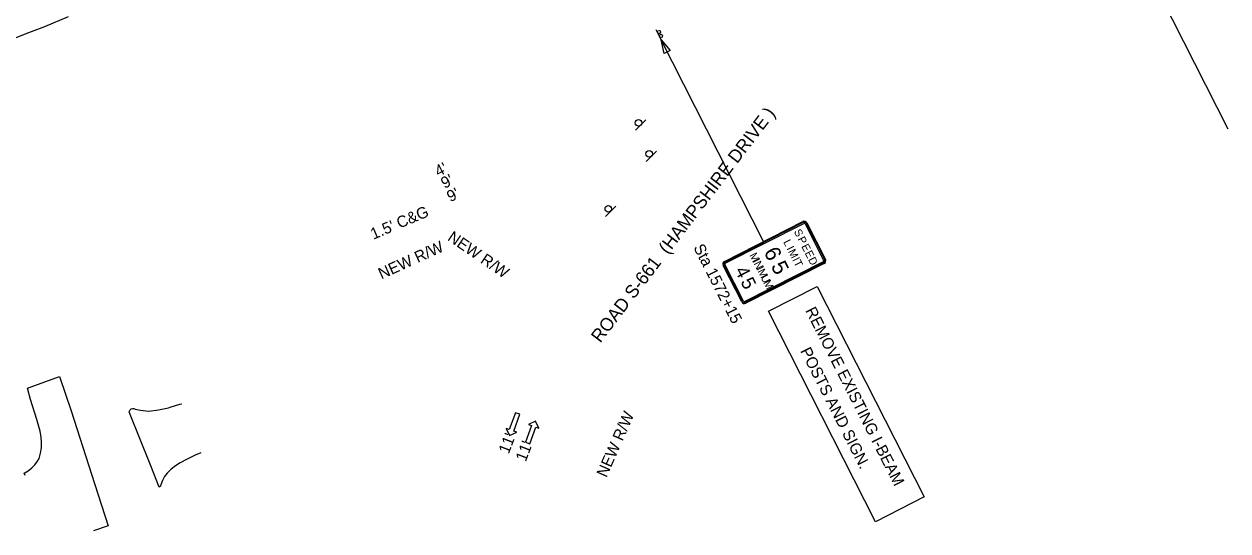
# Model space of a CAD drawing. Extents: x 1803351 to 1804929, y 1187729 to 1188936.
# Drawn here: x 1804190 to 1804929, y 1188019 to 1188330 of the extents above; entities that cross this region are included whole.
import ezdxf

# ---------------------------------------------------------------- set-up
doc = ezdxf.new("R2010")
doc.units = 0
for name, color, linetype in [('RD_EX_RW', 7, 'Continuous'), ('RD_PD_Final_LnLine', 7, 'Continuous'), ('RD_PD_Final_TX', 7, 'Continuous'), ('RD_SHT_MatchLine', 7, 'Continuous'), ('RD_TX_RoadID', 7, 'Continuous'), ('Survey Property', 7, 'Continuous'), ('Survey ROW', 7, 'Continuous')]:
    doc.layers.add(name, color=color, linetype=linetype)

# ---------------------------------------------------------------- blocks, each defined once
blk = doc.blocks.new('SARRW2')
at = {"layer": 'RD_PD_Final_LnLine'}
blk.add_lwpolyline([(-12, 1.2), (-12, -1.2), (-2.83, -1.2), (-2.83, -2.83), (0, 0), (-2.83, 2.83), (-2.83, 1.2)], close=True, dxfattribs=at)

msp = doc.modelspace()

# ---------------------------------------------------------------- linework, layer by layer
at = {"layer": 'RD_EX_RW'}
for points in [[(1804169.94, 1188315.6), (1804193.25, 1188324.71), (1804202.99, 1188328.47), (1804217.7, 1188334.5)], [(1804190.95, 1188052.67), (1804190.4, 1188054.17), (1804192.83, 1188055.56), (1804195.03, 1188057.27), (1804196.97, 1188059.27), (1804198.61, 1188061.53), (1804199.53, 1188063.18), (1804200.44, 1188066.39), (1804200.97, 1188069.69), (1804201.11, 1188073.02), (1804200.85, 1188076.35), (1804200.21, 1188079.62), (1804200.14, 1188079.87), (1804198.14, 1188086.96), (1804194.37, 1188099.36), (1804192.36, 1188106.3), (1804212.17, 1188113.53), (1804219.18, 1188092.31), (1804231.66, 1188053.57), (1804242, 1188021.68), (1804232.98, 1188018.62)], [(1804298.78, 1188066.49), (1804295.27, 1188065.12), (1804290.36, 1188062.77), (1804286.2, 1188060.43), (1804283.29, 1188058.61), (1804280.61, 1188056.47), (1804278.2, 1188054.04), (1804276.63, 1188052.1), (1804275.29, 1188049.61), (1804274.3, 1188046.95), (1804274.06, 1188046.03), (1804273.25, 1188045.44), (1804268.18, 1188058.55), (1804260.98, 1188076.48), (1804255.91, 1188089.08), (1804254.82, 1188091.83), (1804255.45, 1188092.99), (1804256.12, 1188093.56), (1804256.8, 1188093.89), (1804257.14, 1188093.91), (1804257.64, 1188093.8), (1804258.49, 1188093.47), (1804261.73, 1188092.7), (1804265.03, 1188092.31), (1804266.87, 1188092.27), (1804272.93, 1188093.09), (1804278.93, 1188094.29), (1804280.1, 1188094.57), (1804286.01, 1188096.4), (1804287.09, 1188096.76)]]:
    msp.add_lwpolyline(points, dxfattribs=at)
at = {"layer": 'RD_SHT_MatchLine'}
msp.add_line((1804681.38, 1188753.67), (1804929.39, 1188265.47), dxfattribs=at)
at = {"layer": 'Survey Property'}
for p, q in [((1804578.21, 1188326.59), (1804580.22, 1188322.56)), ((1804579.45, 1188324.17), (1804581.47, 1188320.15)), ((1804579.45, 1188324.17), (1804581.47, 1188320.15)), ((1804644.37, 1188196.35), (1804581.47, 1188320.15)), ((1804565.73, 1188264.67), (1804572.09, 1188271.03)), ((1804572.32, 1188245.57), (1804578.68, 1188251.94)), ((1804547.25, 1188211.75), (1804553.61, 1188218.11)), ((1804620.3, 1188184.12), (1804668.44, 1188208.58)), ((1804670.86, 1188207.79), (1804682.27, 1188185.32)), ((1804630.92, 1188159.23), (1804619.51, 1188181.7)), ((1804681.48, 1188182.9), (1804633.34, 1188158.44)), ((1804647.27, 1188153.52), (1804677.24, 1188168.75)), ((1804677.24, 1188168.75), (1804742.92, 1188039.46)), ((1804712.95, 1188024.23), (1804647.27, 1188153.52)), ((1804742.92, 1188039.46), (1804712.95, 1188024.23))]:
    msp.add_line(p, q, dxfattribs=at)
msp.add_lwpolyline([(1804583.36, 1188311.91), (1804581.47, 1188320.15), (1804587.01, 1188313.77)], close=True, dxfattribs=at)
for points in [[(1804620.5, 1188183.72), (1804668.64, 1188208.17)], [(1804620.84, 1188183.05), (1804668.98, 1188207.51)], [(1804669.79, 1188207.24), (1804681.2, 1188184.78)], [(1804670.46, 1188207.58), (1804681.87, 1188185.12)], [(1804631.32, 1188159.43), (1804619.91, 1188181.9)], [(1804631.99, 1188159.77), (1804620.58, 1188182.24)], [(1804680.94, 1188183.97), (1804632.8, 1188159.51)], [(1804681.28, 1188183.3), (1804633.14, 1188158.84)]]:
    msp.add_lwpolyline(points, dxfattribs=at)
for centre, radius in [((1804580.12, 1188325.02), 1), ((1804581.37, 1188322.61), 1), ((1804581.37, 1188322.61), 1), ((1804567.49, 1188269.29), 2), ((1804574.08, 1188250.2), 2), ((1804549.01, 1188216.38), 2)]:
    msp.add_circle(centre, radius, dxfattribs=at)
for centre, radius, start, end in [((1804669.25, 1188206.97), 1.8, 26.93166, 116.93166), ((1804669.25, 1188206.97), 1.35, 26.93166, 116.93166), ((1804669.25, 1188206.97), 0.6, 26.93166, 116.93166), ((1804680.67, 1188184.5), 0.6, 296.93166, 26.93166), ((1804680.67, 1188184.5), 1.35, 296.93166, 26.93166), ((1804680.67, 1188184.5), 1.8, 296.93166, 26.93166), ((1804621.11, 1188182.51), 1.8, 116.93166, 206.93166), ((1804621.11, 1188182.51), 1.35, 116.93166, 206.93166), ((1804621.11, 1188182.51), 0.6, 116.93166, 206.93166), ((1804632.52, 1188160.05), 1.8, 206.93166, 296.93166), ((1804632.52, 1188160.05), 1.35, 206.93166, 296.93166), ((1804632.52, 1188160.05), 0.6, 206.93166, 296.93166)]:
    msp.add_arc(centre, radius, start, end, dxfattribs=at)

# ---------------------------------------------------------------- block references
at = {"layer": 'RD_PD_Final_LnLine'}
for p, xscale, yscale, rotation in [((1804488.41, 1188077.22), 1.2000000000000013, 1.2000000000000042, -109.9498965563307), ((1804504.39, 1188086.11), 1.2000000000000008, 1.2000000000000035, 70.05010344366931)]:
    msp.add_blockref('SARRW2', p, dxfattribs=dict(at, xscale=xscale, yscale=yscale, rotation=rotation))

# ---------------------------------------------------------------- texts
at = {"layer": 'RD_PD_Final_TX'}
for s, rotation, p in [("4'", 26.93166, (1804444.64, 1188235.91)), ("9'", 26.93166, (1804448.43, 1188228.63)), ("9'", 26.93166, (1804452.05, 1188220.38)), ("1.5' C&G", 22.96489, (1804404.79, 1188197.43)), ("11'", 68.95388, (1804487.84, 1188065.49)), ("11'", 68.95388, (1804498.3, 1188060.74))]:
    msp.add_text(s, height=7, rotation=rotation, dxfattribs=at).set_placement(p)
at = {"layer": 'RD_TX_RoadID'}
msp.add_text('ROAD S-661  (HAMPSHIRE DRIVE )', height=8, rotation=52.66554, dxfattribs=at).set_placement((1804544.1, 1188133.66))
at = {"layer": 'Survey Property'}
for s, height, rotation, p in [('S', 4.8, 296.93166, (1804662.77, 1188202.51)), ('P', 4.8, 296.93166, (1804665.08, 1188197.96)), ('Sta 1572+15', 7, 296.93174, (1804601.08, 1188192.76)), ('6', 9.6, 296.93166, (1804644.23, 1188189.99)), ('L', 4.8, 296.93166, (1804656.27, 1188196.1)), ('I', 4.8, 296.93166, (1804658.31, 1188192.08)), ('E', 4.8, 296.93166, (1804667.39, 1188193.41)), ('M', 4.8, 296.93166, (1804635.48, 1188188.02)), ('I', 4.8, 296.93166, (1804637.34, 1188184.34)), ('5', 9.6, 296.93166, (1804648.59, 1188181.4)), ('M', 4.8, 296.93166, (1804659.25, 1188190.24)), ('I', 4.8, 296.93166, (1804661.81, 1188185.19)), ('T', 4.8, 296.93166, (1804662.63, 1188183.57)), ('E', 4.8, 296.93166, (1804669.45, 1188189.36)), ('D', 4.8, 296.93166, (1804671.51, 1188185.31)), ('4', 8.4, 296.93166, (1804626.46, 1188178.61)), ('N', 4.8, 296.93166, (1804638.11, 1188182.84)), ('I', 4.8, 296.93166, (1804639.75, 1188179.6)), ('M', 4.8, 296.93166, (1804640.52, 1188178.09)), ('5', 8.4, 296.93166, (1804629.97, 1188171.7)), ('U', 4.8, 296.93166, (1804642.38, 1188174.42)), ('M', 4.8, 296.93166, (1804644.03, 1188171.18)), ('REMOVE EXISTING I-BEAM', 6.9998, 296.93174, (1804669.74, 1188154.01)), ('POSTS AND SIGN. ', 6.9998, 296.93174, (1804666.64, 1188129.21))]:
    msp.add_text(s, height=height, rotation=rotation, dxfattribs=at).set_placement(p)
at = {"layer": 'Survey ROW'}
for rotation, p in [(325.68189, (1804449.77, 1188197.48)), (24.39241, (1804409.72, 1188173.03)), (66.23619, (1804547.85, 1188051))]:
    msp.add_text('NEW R/W', height=7, rotation=rotation, dxfattribs=at).set_placement(p)

doc.saveas('drawing.dxf')
